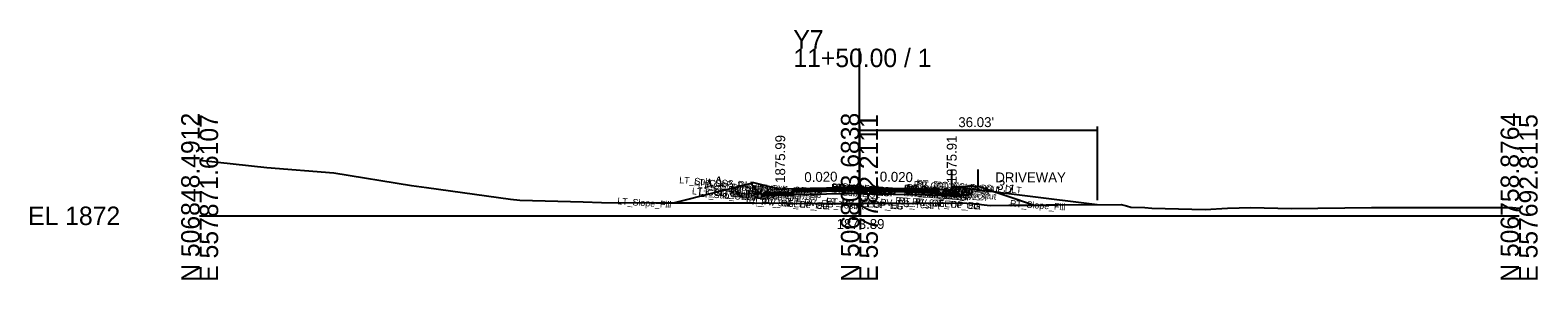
# Model space of a CAD drawing. Extents: x -26 to 557959, y -10 to 506992.
# Drawn here: x -25.7 to 202.8, y 1490.3 to 1528.1 of the extents above; entities that cross this region are included whole.
import ezdxf

# ---------------------------------------------------------------- set-up
doc = ezdxf.new("R2010")
doc.units = 0
for name, color, linetype in [('Default', 7, 'Continuous'), ('Exist CMT Pavement', 7, 'Continuous'), ('Exist Cross Section Cell', 7, 'Continuous'), ('Exist XS Center Line Elevation Label', 7, 'Continuous'), ('Exist XS Ground Line', 7, 'Continuous'), ('Prop CMT Conc Surface', 7, 'Continuous'), ('Prop CMT Concrete Structures', 7, 'Continuous'), ('Prop CMT Pvmt Course 1', 7, 'Continuous'), ('Prop CMT Pvmt Course 1 CG', 7, 'Continuous'), ('Prop CMT Pvmt Course 1 Wedge', 7, 'Continuous'), ('Prop CMT Pvmt Course 2', 7, 'Continuous'), ('Prop CMT Pvmt Course 2 Wedge', 7, 'Continuous'), ('Prop CMT Pvmt Course 3', 7, 'Continuous'), ('Prop CMT Pvmt Course 3 Wedge', 7, 'Continuous'), ('Prop CMT Pvmt Surface', 7, 'Continuous'), ('Prop CMT Pvmt Wedge Surface 1', 7, 'Continuous'), ('Prop CMT Pvmt Wedge Surface 2', 7, 'Continuous'), ('Prop CMT Pvmt Wedge Surface 3', 7, 'Continuous'), ('Prop CMT Shld Paved Course 1', 7, 'Continuous'), ('Prop CMT Shld Paved Course 2', 7, 'Continuous'), ('Prop CMT Shld Paved Course 3', 7, 'Continuous'), ('Prop CMT Slope Grass', 7, 'Continuous'), ('Prop CMT Subgrade Earthwork', 7, 'Continuous'), ('Prop XS Hydro Elevations', 7, 'Continuous'), ('Prop XS Label Text', 7, 'Continuous'), ('Prop XS SE Text', 7, 'Continuous'), ('Prop XS Side Slope Text', 7, 'Continuous'), ('Scratch_Level_0', 7, 'Continuous'), ('Scratch_Level_1', 7, 'Continuous'), ('Typical Text Asphalt at Bridge Approach CELL', 7, 'Continuous')]:
    doc.layers.add(name, color=color, linetype=linetype)

msp = doc.modelspace()

# ---------------------------------------------------------------- linework, layer by layer
at = {"layer": 'Exist CMT Pavement'}
for points in [[(94.32, 1501.87), (100, 1501.89)], [(105.69, 1501.92), (100, 1501.89)]]:
    msp.add_lwpolyline(points, dxfattribs=at)
at = {"layer": 'Exist Cross Section Cell'}
for p, q in [((100, 1500), (100, 1525.32)), ((0, 1500), (100, 1500)), ((100, 1500), (200, 1500))]:
    msp.add_line(p, q, dxfattribs=at)
at = {"layer": 'Exist XS Ground Line'}
for p, q in [((0, 1508.44), (10.2, 1507.3)), ((10.2, 1507.3), (20.32, 1506.49)), ((20.32, 1506.49), (32.09, 1504.59)), ((32.09, 1504.59), (34.39, 1504.27)), ((34.39, 1504.27), (47.13, 1502.5)), ((47.13, 1502.5), (48.55, 1502.35)), ((48.55, 1502.35), (58.11, 1502.1)), ((58.11, 1502.1), (60.92, 1502.03)), ((60.92, 1502.03), (69.13, 1501.98)), ((69.13, 1501.98), (84.1, 1501.97)), ((84.1, 1501.97), (93.3, 1501.87)), ((93.3, 1501.87), (100, 1501.89)), ((100, 1501.89), (109.23, 1501.93)), ((109.23, 1501.93), (115.64, 1501.95)), ((115.64, 1501.95), (117.59, 1501.8)), ((117.59, 1501.8), (119.8, 1501.57)), ((119.8, 1501.57), (122.65, 1501.61)), ((122.65, 1501.61), (127.87, 1501.63)), ((127.87, 1501.63), (128.43, 1501.64)), ((128.43, 1501.64), (129.49, 1501.68)), ((129.49, 1501.68), (130.07, 1501.65)), ((130.07, 1501.65), (139.7, 1501.74)), ((139.7, 1501.74), (140.51, 1501.51)), ((140.51, 1501.51), (141.13, 1501.32)), ((141.13, 1501.32), (143.26, 1501.26)), ((143.26, 1501.26), (144.34, 1501.15)), ((144.34, 1501.15), (152.41, 1500.96)), ((152.41, 1500.96), (155.79, 1501.15)), ((155.79, 1501.15), (159.32, 1501.25)), ((159.32, 1501.25), (165.43, 1501.13)), ((165.43, 1501.13), (177.63, 1501.27)), ((177.63, 1501.27), (197.71, 1501.24)), ((197.71, 1501.24), (199.02, 1501.27)), ((199.02, 1501.27), (200, 1501.16))]:
    msp.add_line(p, q, dxfattribs=at)
at = {"layer": 'Prop CMT Conc Surface'}
for points in [[(90, 1504.07), (88, 1503.99), (86, 1504.49)], [(112, 1504.03), (114, 1503.91)], [(114, 1503.91), (114, 1504.41), (114.5, 1504.41)]]:
    msp.add_lwpolyline(points, dxfattribs=at)
at = {"layer": 'Prop CMT Concrete Structures'}
for points in [[(90, 1504.07), (88, 1503.99), (86, 1504.49)], [(86, 1504.49), (86, 1503.48)], [(90, 1503.48), (90, 1504.07)], [(112, 1504.03), (114, 1503.91), (114, 1504.41), (114.5, 1504.41)], [(114.5, 1504.41), (114.5, 1503.39), (112, 1503.44)], [(112, 1503.44), (112, 1504.03)], [(86, 1503.48), (88, 1503.48), (90, 1503.48)]]:
    msp.add_lwpolyline(points, dxfattribs=at)
at = {"layer": 'Prop CMT Pvmt Course 1'}
for points in [[(100, 1504.27), (90, 1504.07)], [(90, 1503.94), (100, 1504.14)], [(90, 1504.07), (90, 1503.82), (90, 1503.82), (90, 1503.94)], [(100, 1504.02), (100, 1504.27)], [(100, 1504.27), (100, 1504.02)], [(100, 1504.27), (112, 1504.03)], [(100, 1504.02), (100, 1504.27)], [(100, 1504.14), (100, 1504.02), (100, 1504.02)], [(112, 1503.9), (100, 1504.14)], [(100, 1504.14), (100, 1504.02), (100, 1504.02)], [(112, 1504.03), (112, 1503.78), (112, 1503.78), (112, 1503.9)]]:
    msp.add_lwpolyline(points, dxfattribs=at)
at = {"layer": 'Prop CMT Pvmt Course 1 CG'}
for points in [[(90, 1503.48), (85.5, 1503.48), (85.21, 1503.19)], [(85.21, 1503.19), (90, 1503.19)], [(90, 1503.19), (90, 1503.48)], [(112, 1503.44), (115, 1503.38), (115.3, 1503.08)], [(112, 1503.15), (112, 1503.44)], [(115.3, 1503.08), (112, 1503.15)]]:
    msp.add_lwpolyline(points, dxfattribs=at)
at = {"layer": 'Prop CMT Pvmt Course 1 Wedge'}
for points in [[(100, 1504.14), (90, 1503.94)], [(100, 1504.14), (112, 1503.9)]]:
    msp.add_lwpolyline(points, dxfattribs=at)
at = {"layer": 'Prop CMT Pvmt Course 2'}
for points in [[(90, 1503.57), (90, 1503.57), (90, 1503.82), (90, 1503.82)], [(90, 1503.82), (90, 1503.57)], [(100, 1503.77), (100, 1504.02)], [(112, 1503.53), (112, 1503.53), (112, 1503.78), (112, 1503.78)], [(112, 1503.78), (112, 1503.53)]]:
    msp.add_lwpolyline(points, dxfattribs=at)
at = {"layer": 'Prop CMT Pvmt Course 2 Wedge'}
for points in [[(100, 1504.02), (90, 1503.82)], [(100, 1504.02), (112, 1503.78)]]:
    msp.add_lwpolyline(points, dxfattribs=at)
at = {"layer": 'Prop CMT Pvmt Course 3'}
for points in [[(100, 1503.77), (100, 1503.39)], [(90, 1503.57), (90, 1503.57), (90, 1503.19), (90, 1503.19)], [(90, 1503.19), (90, 1503.57)], [(112, 1503.53), (112, 1503.53), (112, 1503.15), (112, 1503.15)], [(112, 1503.15), (112, 1503.53)]]:
    msp.add_lwpolyline(points, dxfattribs=at)
at = {"layer": 'Prop CMT Pvmt Course 3 Wedge'}
for points in [[(100, 1503.77), (90, 1503.57)], [(100, 1503.77), (112, 1503.53)]]:
    msp.add_lwpolyline(points, dxfattribs=at)
at = {"layer": 'Prop CMT Pvmt Surface'}
for points in [[(100, 1504.27), (90, 1504.07)], [(100, 1504.27), (112, 1504.03)]]:
    msp.add_lwpolyline(points, dxfattribs=at)
at = {"layer": 'Prop CMT Pvmt Wedge Surface 1'}
for points in [[(100, 1504.14), (90, 1503.94)], [(90, 1503.82), (90, 1504.07)], [(90, 1503.94), (90, 1503.82), (90, 1503.82)], [(100, 1504.27), (100, 1504.02)], [(100, 1504.14), (112, 1503.9)], [(112, 1503.78), (112, 1504.03)], [(112, 1503.9), (112, 1503.78), (112, 1503.78)]]:
    msp.add_lwpolyline(points, dxfattribs=at)
at = {"layer": 'Prop CMT Pvmt Wedge Surface 2'}
for points in [[(90, 1503.82), (90, 1504.07)], [(100, 1504.02), (90, 1503.82)], [(100, 1504.27), (100, 1504.02)], [(100, 1504.02), (112, 1503.78)], [(112, 1503.78), (112, 1504.03)]]:
    msp.add_lwpolyline(points, dxfattribs=at)
at = {"layer": 'Prop CMT Pvmt Wedge Surface 3'}
for points in [[(90, 1503.57), (90, 1504.07)], [(100, 1503.77), (90, 1503.57)], [(100, 1504.27), (100, 1503.77)], [(100, 1503.77), (112, 1503.53)], [(112, 1503.53), (112, 1504.03)]]:
    msp.add_lwpolyline(points, dxfattribs=at)
at = {"layer": 'Prop CMT Shld Paved Course 1'}
for points in [[(90, 1504.07), (90, 1503.82)], [(90, 1503.82), (90, 1504.07)]]:
    msp.add_lwpolyline(points, dxfattribs=at)
at = {"layer": 'Prop CMT Shld Paved Course 2'}
for points in [[(90, 1503.82), (90, 1503.57)], [(90, 1503.57), (90, 1503.82)]]:
    msp.add_lwpolyline(points, dxfattribs=at)
at = {"layer": 'Prop CMT Shld Paved Course 3'}
for points in [[(90, 1503.57), (90, 1503.19)], [(90, 1503.19), (90, 1503.57)]]:
    msp.add_lwpolyline(points, dxfattribs=at)
at = {"layer": 'Prop CMT Slope Grass'}
msp.add_line((114.5, 1504.41), (136.03, 1501.71), dxfattribs=at)
msp.add_lwpolyline([(86, 1504.49), (84, 1504.99), (71.96, 1501.98)], dxfattribs=at)
at = {"layer": 'Prop CMT Subgrade Earthwork'}
for points in [[(90, 1503.19), (85.21, 1503.19), (83.53, 1504.87)], [(100, 1503.39), (115.3, 1503.08), (116.38, 1504.17)], [(100, 1503.39), (90, 1503.19)], [(90, 1503.19), (90, 1503.19)], [(112, 1503.15), (112, 1503.15)]]:
    msp.add_lwpolyline(points, dxfattribs=at)
at = {"layer": 'Prop XS Label Text'}
for p, q in [((100, 1513.54), (100, 1504.48)), ((136.03, 1512.93), (100, 1512.93)), ((136.03, 1513.54), (136.03, 1502.35))]:
    msp.add_line(p, q, dxfattribs=at)
at = {"layer": 'Scratch_Level_0'}
msp.add_line((118, 1504.48), (126.54, 1501.63), dxfattribs=at)
msp.add_lwpolyline([(114.5, 1504.41), (118, 1504.48)], dxfattribs=at)
at = {"layer": 'Scratch_Level_1'}
for p, q in [((114, 1504.41), (114, 1507.04)), ((118, 1504.41), (118, 1507.04))]:
    msp.add_line(p, q, dxfattribs=at)

# ---------------------------------------------------------------- texts
at = {"layer": 'Default'}
msp.add_text('-', height=0.0001, dxfattribs=at).set_placement((0, 1500))
at = {"layer": 'Exist Cross Section Cell'}
for s, p in [('Y7', (90, 1525.32)), ('11+50.00 / 1', (90, 1522.52)), ('EL 1872', (-26, 1498.6))]:
    msp.add_text(s, height=2.8, dxfattribs=at).set_placement(p)
for s, p in [('N 506848.4912', (0, 1490)), ('E 557871.6107', (2.8, 1490)), ('N 506803.6838', (100, 1490)), ('E 557782.2111', (102.8, 1490)), ('N 506758.8764', (200, 1490)), ('E 557692.8115', (202.8, 1490))]:
    msp.add_text(s, height=2.8, rotation=90, dxfattribs=at).set_placement(p)
at = {"layer": 'Exist XS Center Line Elevation Label'}
msp.add_text('1873.89', height=1.5, dxfattribs=at).set_placement((96.55, 1498.01))
at = {"layer": 'Prop XS Hydro Elevations'}
for s, p in [('1875.99', (88.75, 1504.99)), ('1875.91', (114.75, 1504.91))]:
    msp.add_text(s, height=1.5, rotation=90, dxfattribs=at).set_placement(p)
at = {"layer": 'Prop XS Label Text'}
for s, p in [("36.03'", (115, 1513.43)), ('DRIVEWAY', (120.6, 1505.07))]:
    msp.add_text(s, height=1.5, rotation=0.0969, dxfattribs=at).set_placement(p)
at = {"layer": 'Prop XS SE Text'}
for rotation, p in [(1.1458, (91.67, 1505.1)), (358.8542, (103.08, 1505.2))]:
    msp.add_text('0.020', height=1.5, rotation=rotation, dxfattribs=at).set_placement(p)
at = {"layer": 'Prop XS Side Slope Text'}
msp.add_text('4:1', height=1.5, rotation=14.0364, dxfattribs=at).set_placement((76.89, 1503.98))
at = {"layer": 'Scratch_Level_0'}
msp.add_text('3:1', height=1.5, rotation=337.964, dxfattribs=at).set_placement((120.65, 1504.17))
at = {"layer": 'Typical Text Asphalt at Bridge Approach CELL'}
for s, p in [('LT_Sub_OSS_DLT', (72.67, 1504.94)), ('LT_CG1_Shelf_Out', (74.6, 1503.26)), ('LT_CSLP_Pnt', (74.91, 1504.64)), ('LT_CG_Top_BOC', (75.51, 1504.24)), ('LT_Sub_OEOP', (75.58, 1502.88)), ('LT_CG_Bot_BOC', (75.65, 1503.22)), ('LT_CG_Top_Gut', (77.79, 1503.72)), ('LT_CG_Bot_Gut', (77.93, 1503.2)), ('LT_Sub_Trench_Out', (78.72, 1503)), ('LT_PS2_OEOP', (80.39, 1503.5)), ('LT_PS3_OEOP', (80.39, 1503.25)), ('LT_PS1_OEOP', (80.51, 1503.75)), ('LT_CG_Bot_IE', (80.53, 1503.16)), ('LT_PV2_OEEOP', (84, 1503.61)), ('LT_PV3_OEEOP', (84, 1503.36)), ('LT_Sub_OEEOP', (84.02, 1502.98)), ('LT_PV1_OEEOP', (84.12, 1503.73)), ('LT_PV2_OEOT', (84.35, 1503.59)), ('LT_PV3_OEOT', (84.35, 1503.34)), ('LT_Sub_OEOT', (84.38, 1502.96)), ('LT_PV1_OEOT', (84.47, 1503.83)), ('RT_PV2_IEEOP', (95.69, 1503.82)), ('RT_PV3_IEEOP', (95.69, 1503.57)), ('LT_PV2_IEEOP', (95.75, 1503.81)), ('LT_PV3_IEEOP', (95.75, 1503.56)), ('RT_PV1_IEEOP', (95.81, 1503.93)), ('LT_PV1_IEEOP', (95.87, 1503.93)), ('Sub_PGL', (97.35, 1503.08)), ('PV2_PGL', (97.32, 1503.7)), ('PV3_PGL', (97.32, 1503.45)), ('PV1_PGL', (97.44, 1503.94)), ('RT_PV2_OEEOP', (106.68, 1503.62)), ('RT_PV3_OEEOP', (106.68, 1503.37)), ('RT_Sub_OEEOP', (106.71, 1502.99)), ('RT_PV1_OEEOP', (106.8, 1503.73)), ('RT_PV2_OEOT', (107.03, 1503.59)), ('RT_PV3_OEOT', (107.03, 1503.34)), ('RT_Sub_OEOT', (107.06, 1502.96)), ('RT_PV1_OEOT', (107.15, 1503.83)), ('RT_CG_Bot_IE', (107.21, 1503.24)), ('RT_CG_Top_Face', (108.21, 1504.28)), ('RT_CG_Top_Gut', (108.48, 1503.76)), ('RT_Sub_Trench_Out_DLT', (108.61, 1504.48)), ('RT_CG_Top_BOC', (108.7, 1504.28)), ('RT_CG1_Shelf_Out', (108.78, 1503.28)), ('RT_CG_Bot_BOC', (108.83, 1503.26)), ('RT_Sub_OEOP', (110.35, 1502.9)), ('RT_CSLP_Pnt', (111.59, 1504.21)), ('LT_Slope_Fill', (63.29, 1501.75)), ('LT_PV_Sub_Tie_Out', (82.79, 1501.83)), ('LT_PV_OEEOP_EG', (83.21, 1501.8)), ('LT_PV_EG_TestPt', (89.33, 1501.72)), ('RT_PV_IEEOP_EG', (94.9, 1501.75)), ('LT_PV_IEEOP_EG', (94.96, 1501.75)), ('RT_PV_EG_TestPt', (100.65, 1501.77)), ('RT_PV_Sub_Tie_Out', (105.44, 1501.85)), ('RT_PV_OEEOP_EG', (105.89, 1501.82)), ('RT_Slope_Fill', (122.8, 1501.4))]:
    msp.add_text(s, height=1, rotation=356, dxfattribs=at).set_placement(p)

doc.saveas('drawing.dxf')
